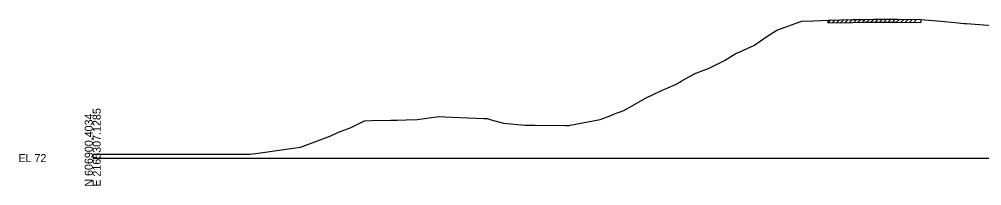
# Model space of a CAD drawing. Extents: x -26 to 6803, y -10 to 19606.
# Drawn here: x 3974.3 to 4310.9, y 16990.3 to 17048.7 of the extents above; entities that cross this region are included whole.
import ezdxf

# ---------------------------------------------------------------- set-up
doc = ezdxf.new("R2010")
doc.units = 0
for name, color, linetype in [('RD_GPK_XS_Cell', 7, 'Continuous'), ('RD_XS_ExGround', 7, 'Continuous'), ('RD_XS_ExPaveRet', 7, 'Continuous')]:
    doc.layers.add(name, color=color, linetype=linetype)

msp = doc.modelspace()

# ---------------------------------------------------------------- linework, layer by layer
at = {"layer": 'RD_GPK_XS_Cell'}
msp.add_line((4000, 17000), (4400, 17000), dxfattribs=at)
at = {"layer": 'RD_XS_ExGround'}
msp.add_lwpolyline([(4000, 17001.34), (4038.89, 17001.34), (4055.08, 17001.34), (4055.81, 17001.44), (4057, 17001.62), (4067.71, 17003.09), (4072.67, 17003.89), (4079.53, 17006.39), (4083.34, 17007.81), (4086, 17009.04), (4090.36, 17010.7), (4095.04, 17013.09), (4097.53, 17013.15), (4104.22, 17013.24), (4106.5, 17013.28), (4109.58, 17013.36), (4113.62, 17013.49), (4117.65, 17014.09), (4121.02, 17014.52), (4123.17, 17014.5), (4134.04, 17013.98), (4136.77, 17013.92), (4137.95, 17013.86), (4139.32, 17013.4), (4143.69, 17012.26), (4151.2, 17011.58), (4152.63, 17011.5), (4154.71, 17011.5), (4165.35, 17011.43), (4166.63, 17011.42), (4167.04, 17011.5), (4177.43, 17013.51), (4181.22, 17014.91), (4183.02, 17015.73), (4184.18, 17016.15), (4185.8, 17016.69), (4188.65, 17018.34), (4193.28, 17020.97), (4196.03, 17022.23), (4198.5, 17023.4), (4203.8, 17025.77), (4205.86, 17027), (4210.27, 17029.41), (4210.58, 17029.62), (4210.94, 17029.76), (4215.58, 17031.46), (4217, 17032.22), (4220.98, 17034.18), (4224.69, 17036.58), (4226.3, 17037.26), (4231.43, 17039.56), (4235.43, 17042.35), (4239.3, 17044.81), (4247.31, 17047.72), (4247.96, 17047.95), (4252.13, 17048.14), (4257.18, 17048.38), (4265.88, 17048.55), (4269.81, 17048.6), (4273.23, 17048.62), (4274.73, 17048.65), (4281.53, 17048.63), (4289.62, 17048.5), (4296.64, 17047.96), (4301.67, 17047.53), (4304.7, 17047.2), (4305.6, 17047.12), (4319.21, 17046.11)], dxfattribs=at)
at = {"layer": 'RD_XS_ExPaveRet'}
for p, q in [((4257.18, 17047.38), (4258.2, 17048.4)), ((4257.18, 17047.38), (4257.18, 17048.38)), ((4257.18, 17047.38), (4265.88, 17047.55)), ((4258.68, 17047.41), (4259.7, 17048.43)), ((4260.18, 17047.44), (4261.2, 17048.46)), ((4261.68, 17047.47), (4262.7, 17048.49)), ((4263.18, 17047.5), (4264.2, 17048.52)), ((4264.68, 17047.53), (4265.7, 17048.55)), ((4265.88, 17047.55), (4269.81, 17047.6)), ((4266.18, 17047.56), (4267.19, 17048.57)), ((4267.68, 17047.57), (4268.69, 17048.59)), ((4269.18, 17047.59), (4270.19, 17048.6)), ((4269.81, 17047.6), (4273.23, 17047.62)), ((4270.68, 17047.61), (4271.68, 17048.61)), ((4272.18, 17047.61), (4273.18, 17048.62)), ((4273.23, 17047.62), (4274.73, 17047.65)), ((4273.68, 17047.63), (4274.7, 17048.65)), ((4274.73, 17047.65), (4281.53, 17047.63)), ((4275.18, 17047.65), (4276.18, 17048.65)), ((4276.68, 17047.65), (4277.68, 17048.64)), ((4278.18, 17047.64), (4279.18, 17048.64)), ((4279.68, 17047.63), (4280.68, 17048.63)), ((4281.18, 17047.63), (4282.17, 17048.62)), ((4281.53, 17047.63), (4289.62, 17047.5)), ((4282.68, 17047.61), (4283.66, 17048.59)), ((4284.18, 17047.59), (4285.16, 17048.57)), ((4285.68, 17047.56), (4286.66, 17048.55)), ((4287.18, 17047.54), (4288.16, 17048.52)), ((4289.62, 17048.5), (4289.62, 17047.5))]:
    msp.add_line(p, q, dxfattribs=at)

# ---------------------------------------------------------------- texts
at = {"layer": 'RD_GPK_XS_Cell'}
for s, p in [('E 2165307.1285', (4002.8, 16990)), ('N 606900.4034', (4000, 16990))]:
    msp.add_text(s, height=2.8, rotation=90, dxfattribs=at).set_placement(p)
msp.add_text('EL 72', height=2.8, dxfattribs=at).set_placement((3974, 16998.6))

doc.saveas('drawing.dxf')
